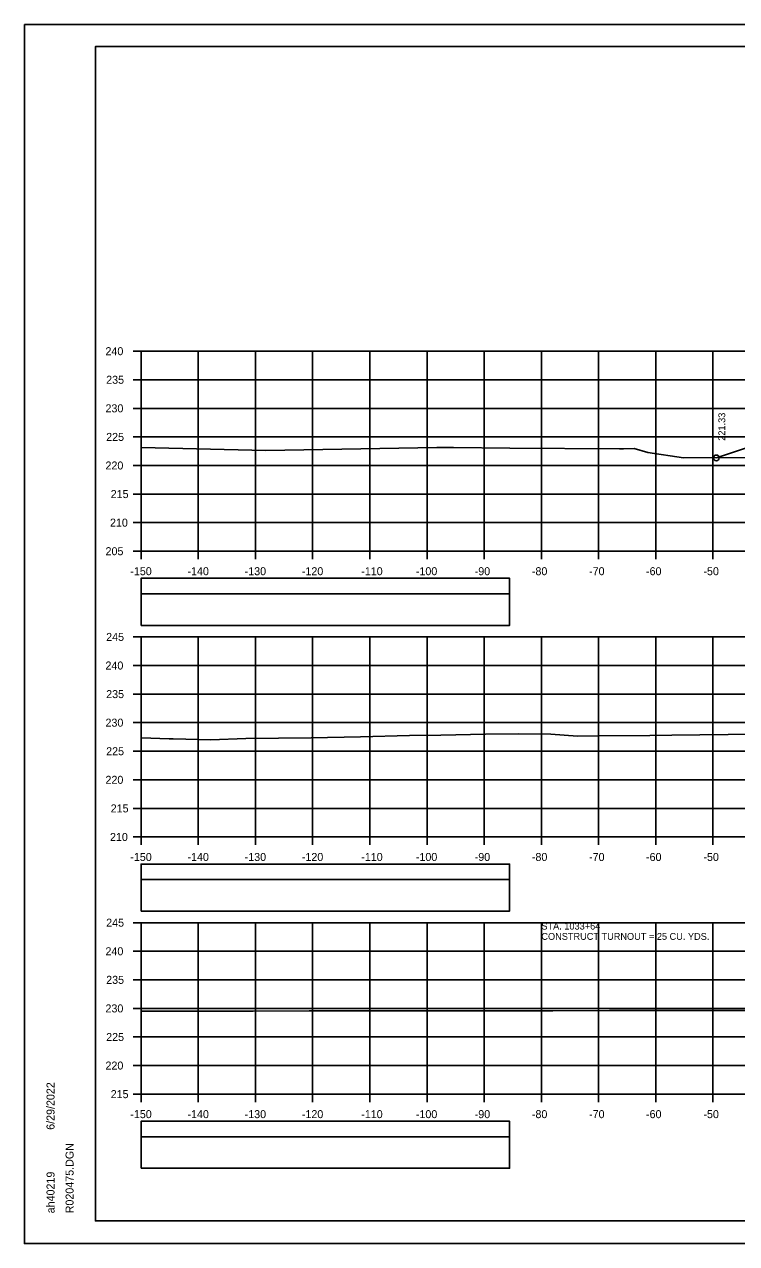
# Model space of a CAD drawing. Extents: x 1386544 to 1388153, y 379785 to 390999.
# Drawn here: x 1387189.3 to 1387313.8, y 386092.2 to 386305.5 of the extents above; entities that cross this region are included whole.
import ezdxf

# ---------------------------------------------------------------- set-up
doc = ezdxf.new("R2010")
doc.units = 0
for name, color, linetype in [('R_Axis', 7, 'Continuous'), ('R_Axis Annot', 7, 'Continuous'), ('R_Border', 7, 'Continuous'), ('R_Drive', 7, 'Continuous'), ('R_Exist Surface', 7, 'Continuous'), ('R_Fin Surface', 7, 'Continuous'), ('R_Grid', 7, 'Continuous'), ('R_No Plot', 7, 'Continuous'), ('R_Xsect Elev', 7, 'Continuous')]:
    doc.layers.add(name, color=color, linetype=linetype)

msp = doc.modelspace()

# ---------------------------------------------------------------- linework, layer by layer
at = {"layer": 'R_Axis'}
for p, q in [((1387208.28, 386248.32), (1387209.68, 386248.32)), ((1387209.68, 386213.32), (1387209.68, 386248.32)), ((1387208.28, 386243.32), (1387209.68, 386243.32)), ((1387208.28, 386238.32), (1387209.68, 386238.32)), ((1387208.28, 386233.32), (1387209.68, 386233.32)), ((1387208.28, 386228.32), (1387209.68, 386228.32)), ((1387208.28, 386223.32), (1387209.68, 386223.32)), ((1387208.28, 386218.32), (1387209.68, 386218.32)), ((1387208.28, 386213.32), (1387209.68, 386213.32)), ((1387209.68, 386213.32), (1387509.68, 386213.32)), ((1387209.68, 386211.92), (1387209.68, 386213.32)), ((1387219.68, 386211.92), (1387219.68, 386213.32)), ((1387229.68, 386211.92), (1387229.68, 386213.32)), ((1387239.68, 386211.92), (1387239.68, 386213.32)), ((1387249.68, 386211.92), (1387249.68, 386213.32)), ((1387259.68, 386211.92), (1387259.68, 386213.32)), ((1387269.68, 386211.92), (1387269.68, 386213.32)), ((1387279.68, 386211.92), (1387279.68, 386213.32)), ((1387289.68, 386211.92), (1387289.68, 386213.32)), ((1387299.68, 386211.92), (1387299.68, 386213.32)), ((1387309.68, 386211.92), (1387309.68, 386213.32)), ((1387208.28, 386198.32), (1387209.68, 386198.32)), ((1387209.68, 386163.32), (1387209.68, 386198.32)), ((1387208.28, 386193.32), (1387209.68, 386193.32)), ((1387208.28, 386188.32), (1387209.68, 386188.32)), ((1387208.28, 386183.32), (1387209.68, 386183.32)), ((1387208.28, 386178.32), (1387209.68, 386178.32)), ((1387208.28, 386173.32), (1387209.68, 386173.32)), ((1387208.28, 386168.32), (1387209.68, 386168.32)), ((1387208.28, 386163.32), (1387209.68, 386163.32)), ((1387209.68, 386163.32), (1387509.68, 386163.32)), ((1387209.68, 386161.92), (1387209.68, 386163.32)), ((1387219.68, 386161.92), (1387219.68, 386163.32)), ((1387229.68, 386161.92), (1387229.68, 386163.32)), ((1387239.68, 386161.92), (1387239.68, 386163.32)), ((1387249.68, 386161.92), (1387249.68, 386163.32)), ((1387259.68, 386161.92), (1387259.68, 386163.32)), ((1387269.68, 386161.92), (1387269.68, 386163.32)), ((1387279.68, 386161.92), (1387279.68, 386163.32)), ((1387289.68, 386161.92), (1387289.68, 386163.32)), ((1387299.68, 386161.92), (1387299.68, 386163.32)), ((1387309.68, 386161.92), (1387309.68, 386163.32)), ((1387208.28, 386148.32), (1387209.68, 386148.32)), ((1387209.68, 386118.32), (1387209.68, 386148.32)), ((1387208.28, 386143.32), (1387209.68, 386143.32)), ((1387208.28, 386138.32), (1387209.68, 386138.32)), ((1387208.28, 386133.32), (1387209.68, 386133.32)), ((1387208.28, 386128.32), (1387209.68, 386128.32)), ((1387208.28, 386123.32), (1387209.68, 386123.32)), ((1387208.28, 386118.32), (1387209.68, 386118.32)), ((1387209.68, 386118.32), (1387509.68, 386118.32)), ((1387209.68, 386116.92), (1387209.68, 386118.32)), ((1387219.68, 386116.92), (1387219.68, 386118.32)), ((1387229.68, 386116.92), (1387229.68, 386118.32)), ((1387239.68, 386116.92), (1387239.68, 386118.32)), ((1387249.68, 386116.92), (1387249.68, 386118.32)), ((1387259.68, 386116.92), (1387259.68, 386118.32)), ((1387269.68, 386116.92), (1387269.68, 386118.32)), ((1387279.68, 386116.92), (1387279.68, 386118.32)), ((1387289.68, 386116.92), (1387289.68, 386118.32)), ((1387299.68, 386116.92), (1387299.68, 386118.32)), ((1387309.68, 386116.92), (1387309.68, 386118.32))]:
    msp.add_line(p, q, dxfattribs=at)
at = {"layer": 'R_Axis Annot'}
for points in [[(1387209.68, 386205.87), (1387274.11, 386205.87), (1387274.11, 386208.58), (1387209.68, 386208.58)], [(1387209.68, 386200.34), (1387274.11, 386200.34), (1387274.11, 386205.87), (1387209.68, 386205.87)], [(1387209.68, 386155.87), (1387274.11, 386155.87), (1387274.11, 386158.58), (1387209.68, 386158.58)], [(1387209.68, 386150.34), (1387274.11, 386150.34), (1387274.11, 386155.87), (1387209.68, 386155.87)], [(1387209.68, 386110.87), (1387274.11, 386110.87), (1387274.11, 386113.58), (1387209.68, 386113.58)], [(1387209.68, 386105.34), (1387274.11, 386105.34), (1387274.11, 386110.87), (1387209.68, 386110.87)]]:
    msp.add_lwpolyline(points, close=True, dxfattribs=at)
at = {"layer": 'R_Border'}
for p, q in [((1387201.68, 386301.61), (1387517.86, 386301.61)), ((1387201.68, 386096.15), (1387201.68, 386301.61)), ((1387201.68, 386096.15), (1387201.68, 386096.15)), ((1387517.86, 386096.15), (1387201.68, 386096.15))]:
    msp.add_line(p, q, dxfattribs=at)
at = {"layer": 'R_Exist Surface'}
for points in [[(1387209.68, 386231.45), (1387231.47, 386230.96), (1387261.37, 386231.45), (1387264.31, 386231.48), (1387274.19, 386231.38), (1387293.34, 386231.24), (1387294.07, 386231.24), (1387295.93, 386231.27), (1387298.3, 386230.6), (1387304.53, 386229.64), (1387321.45, 386229.69)], [(1387209.68, 386180.69), (1387209.75, 386180.68), (1387214.59, 386180.52), (1387215.29, 386180.48), (1387221.9, 386180.32), (1387228, 386180.55), (1387239.44, 386180.66), (1387248.02, 386180.87), (1387256.6, 386181.07), (1387262.09, 386181.11), (1387269.92, 386181.29), (1387275.7, 386181.35), (1387281.35, 386181.32), (1387285.98, 386180.96), (1387289.81, 386180.99), (1387298.62, 386181.08), (1387302.52, 386181.12), (1387307.37, 386181.2), (1387322.22, 386181.34)], [(1387209.68, 386132.81), (1387210.66, 386132.81), (1387217.24, 386132.84), (1387229.25, 386132.86), (1387239.05, 386132.87), (1387247.78, 386132.88), (1387260.77, 386132.89), (1387266.11, 386132.89), (1387281.68, 386132.92), (1387291.58, 386132.94), (1387300.89, 386132.95), (1387302.57, 386132.95), (1387320.04, 386132.95)]]:
    msp.add_lwpolyline(points, dxfattribs=at)
at = {"layer": 'R_Fin Surface'}
msp.add_lwpolyline([(1387310.28, 386229.65), (1387323.68, 386234.12), (1387333.11, 386235.69), (1387339.68, 386236.78), (1387345.68, 386237.02), (1387347.68, 386237.06), (1387359.68, 386237.3), (1387371.68, 386237.5), (1387373.68, 386237.54), (1387379.68, 386237.64), (1387388.56, 386236.16), (1387395.68, 386234.97), (1387415.26, 386228.44)], dxfattribs=at)
at = {"layer": 'R_Grid'}
for p, q in [((1387209.68, 386248.32), (1387509.68, 386248.32)), ((1387209.68, 386213.32), (1387209.68, 386248.32)), ((1387219.68, 386213.32), (1387219.68, 386248.32)), ((1387229.68, 386213.32), (1387229.68, 386248.32)), ((1387239.68, 386213.32), (1387239.68, 386248.32)), ((1387249.68, 386213.32), (1387249.68, 386248.32)), ((1387259.68, 386213.32), (1387259.68, 386248.32)), ((1387269.68, 386213.32), (1387269.68, 386248.32)), ((1387279.68, 386213.32), (1387279.68, 386248.32)), ((1387289.68, 386213.32), (1387289.68, 386248.32)), ((1387299.68, 386213.32), (1387299.68, 386248.32)), ((1387309.68, 386213.32), (1387309.68, 386248.32)), ((1387209.68, 386243.32), (1387509.68, 386243.32)), ((1387209.68, 386238.32), (1387509.68, 386238.32)), ((1387209.68, 386233.32), (1387509.68, 386233.32)), ((1387209.68, 386228.32), (1387509.68, 386228.32)), ((1387209.68, 386223.32), (1387509.68, 386223.32)), ((1387209.68, 386218.32), (1387509.68, 386218.32)), ((1387209.68, 386213.32), (1387509.68, 386213.32)), ((1387209.68, 386198.32), (1387509.68, 386198.32)), ((1387209.68, 386163.32), (1387209.68, 386198.32)), ((1387219.68, 386163.32), (1387219.68, 386198.32)), ((1387229.68, 386163.32), (1387229.68, 386198.32)), ((1387239.68, 386163.32), (1387239.68, 386198.32)), ((1387249.68, 386163.32), (1387249.68, 386198.32)), ((1387259.68, 386163.32), (1387259.68, 386198.32)), ((1387269.68, 386163.32), (1387269.68, 386198.32)), ((1387279.68, 386163.32), (1387279.68, 386198.32)), ((1387289.68, 386163.32), (1387289.68, 386198.32)), ((1387299.68, 386163.32), (1387299.68, 386198.32)), ((1387309.68, 386163.32), (1387309.68, 386198.32)), ((1387209.68, 386193.32), (1387509.68, 386193.32)), ((1387209.68, 386188.32), (1387509.68, 386188.32)), ((1387209.68, 386183.32), (1387509.68, 386183.32)), ((1387209.68, 386178.32), (1387509.68, 386178.32)), ((1387209.68, 386173.32), (1387509.68, 386173.32)), ((1387209.68, 386168.32), (1387509.68, 386168.32)), ((1387209.68, 386163.32), (1387509.68, 386163.32)), ((1387209.68, 386148.32), (1387509.68, 386148.32)), ((1387209.68, 386118.32), (1387209.68, 386148.32)), ((1387219.68, 386118.32), (1387219.68, 386148.32)), ((1387229.68, 386118.32), (1387229.68, 386148.32)), ((1387239.68, 386118.32), (1387239.68, 386148.32)), ((1387249.68, 386118.32), (1387249.68, 386148.32)), ((1387259.68, 386118.32), (1387259.68, 386148.32)), ((1387269.68, 386118.32), (1387269.68, 386148.32)), ((1387279.68, 386118.32), (1387279.68, 386148.32)), ((1387289.68, 386118.32), (1387289.68, 386148.32)), ((1387299.68, 386118.32), (1387299.68, 386148.32)), ((1387309.68, 386118.32), (1387309.68, 386148.32)), ((1387209.68, 386143.32), (1387509.68, 386143.32)), ((1387209.68, 386138.32), (1387509.68, 386138.32)), ((1387209.68, 386133.32), (1387509.68, 386133.32)), ((1387209.68, 386128.32), (1387509.68, 386128.32)), ((1387209.68, 386123.32), (1387509.68, 386123.32)), ((1387209.68, 386118.32), (1387509.68, 386118.32))]:
    msp.add_line(p, q, dxfattribs=at)
at = {"layer": 'R_No Plot'}
for p, q in [((1387189.28, 386305.5), (1387522.61, 386305.5)), ((1387189.28, 386092.17), (1387522.61, 386092.17))]:
    msp.add_line(p, q, dxfattribs=at)
for points in [[(1387189.27, 386305.5), (1387522.61, 386305.5), (1387522.61, 386092.17), (1387189.27, 386092.17)], [(1387435.6, 386301.61), (1387455.22, 386301.61), (1387455.22, 386291.73), (1387471.33, 386291.73), (1387494.53, 386291.73), (1387494.53, 386267.4), (1387517.86, 386267.4), (1387517.86, 386096.15), (1387201.68, 386096.15), (1387201.68, 386301.61)]]:
    msp.add_lwpolyline(points, close=True, dxfattribs=at)
msp.add_circle((1387310.28, 386229.65), 0.5, dxfattribs=at)

# ---------------------------------------------------------------- texts
at = {"layer": 'R_Axis Annot'}
for s, p in [('240', (1387203.45, 386247.62)), ('235', (1387203.57, 386242.62)), ('230', (1387203.45, 386237.62)), ('225', (1387203.57, 386232.62)), ('220', (1387203.45, 386227.62)), ('215', (1387204.36, 386222.62)), ('210', (1387204.24, 386217.62)), ('205', (1387203.46, 386212.62)), ('-150', (1387207.79, 386209.12)), ('-140', (1387217.79, 386209.12)), ('-130', (1387227.79, 386209.12)), ('-120', (1387237.79, 386209.12)), ('-110', (1387248.18, 386209.12)), ('-100', (1387257.73, 386209.12)), ('-90', (1387268.02, 386209.12)), ('-80', (1387278.02, 386209.12)), ('-70', (1387288.02, 386209.12)), ('-60', (1387297.98, 386209.12)), ('-50', (1387308.02, 386209.12)), ('245', (1387203.57, 386197.62)), ('240', (1387203.45, 386192.62)), ('235', (1387203.57, 386187.62)), ('230', (1387203.45, 386182.62)), ('225', (1387203.57, 386177.62)), ('220', (1387203.45, 386172.62)), ('215', (1387204.36, 386167.62)), ('210', (1387204.24, 386162.62)), ('-150', (1387207.79, 386159.12)), ('-140', (1387217.79, 386159.12)), ('-130', (1387227.79, 386159.12)), ('-120', (1387237.79, 386159.12)), ('-110', (1387248.18, 386159.12)), ('-100', (1387257.73, 386159.12)), ('-90', (1387268.02, 386159.12)), ('-80', (1387278.02, 386159.12)), ('-70', (1387288.02, 386159.12)), ('-60', (1387297.98, 386159.12)), ('-50', (1387308.02, 386159.12)), ('245', (1387203.57, 386147.62)), ('240', (1387203.45, 386142.62)), ('235', (1387203.57, 386137.62)), ('230', (1387203.45, 386132.62)), ('225', (1387203.57, 386127.62)), ('220', (1387203.45, 386122.62)), ('215', (1387204.36, 386117.62)), ('-150', (1387207.79, 386114.12)), ('-140', (1387217.79, 386114.12)), ('-130', (1387227.79, 386114.12)), ('-120', (1387237.79, 386114.12)), ('-110', (1387248.18, 386114.12)), ('-100', (1387257.73, 386114.12)), ('-90', (1387268.02, 386114.12)), ('-80', (1387278.02, 386114.12)), ('-70', (1387288.02, 386114.12)), ('-60', (1387297.98, 386114.12)), ('-50', (1387308.02, 386114.12))]:
    msp.add_text(s, height=1.4, dxfattribs=at).set_placement(p)
at = {"layer": 'R_Border'}
for s, p in [('6/29/2022', (1387194.54, 386112.08)), ('R020475.DGN', (1387197.87, 386097.47)), ('ah40219', (1387194.54, 386097.47))]:
    msp.add_text(s, height=1.4, rotation=90, dxfattribs=at).set_placement(p)
at = {"layer": 'R_Drive'}
for s, p in [('STA. 1033+64 ', (1387279.68, 386147.12)), ('CONSTRUCT TURNOUT = 25 CU. YDS.', (1387279.68, 386145.32))]:
    msp.add_text(s, height=1.2, dxfattribs=at).set_placement(p)
at = {"layer": 'R_Xsect Elev'}
msp.add_text('221.33', height=1.2, rotation=90, dxfattribs=at).set_placement((1387311.83, 386232.65))

doc.saveas('drawing.dxf')
